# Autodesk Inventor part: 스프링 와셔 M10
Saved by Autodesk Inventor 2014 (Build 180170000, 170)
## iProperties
Created: 2026-06
Part Number: 스프링 와셔 M10
Material: 일반
Document SubType Name: Modeling
Designer: dg
Density: 1 g/cm^3
Appearance: 기본값
Author: dg
Author: jhkim
Description: 스프링 잠금 와셔
Creation Date: 2026-05-29
Sending System: Autodesk Inventor 2027
Preprocessor: ST-DEVELOPER v20.1
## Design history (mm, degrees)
node "스프링 와셔 M101"
body "Solid1"
node "기준1"
